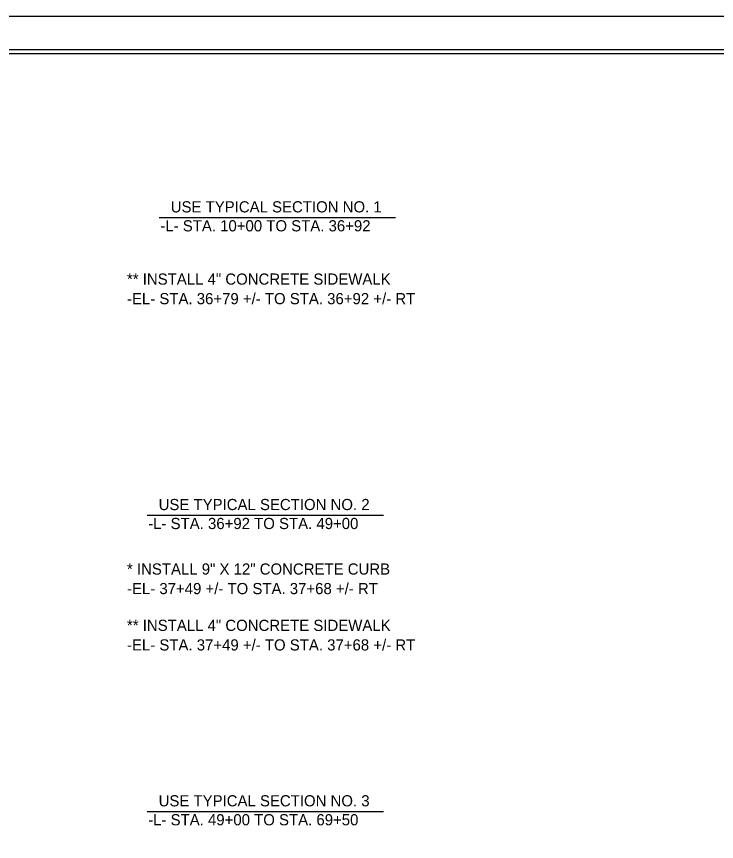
# Model space of a CAD drawing. Extents: x 1022283 to 1026986, y 174822 to 180471.
# Drawn here: x 1024632 to 1025806, y 179087 to 180471 of the extents above; entities that cross this region are included whole.
import ezdxf

# ---------------------------------------------------------------- set-up
doc = ezdxf.new("R2010")
doc.units = 0
for name, color, linetype in [('Prop Dimension', 7, 'Continuous'), ('Sheet Cutting Line CELL', 7, 'Continuous'), ('Sheet Plot Border Inside CELL', 7, 'Continuous'), ('Sheet Plot Border Outside CELL', 7, 'Continuous'), ('Sheet Typical CELL', 7, 'Continuous'), ('Typical Text Label CELL', 7, 'Continuous')]:
    doc.layers.add(name, color=color, linetype=linetype)

msp = doc.modelspace()

# ---------------------------------------------------------------- linework, layer by layer
at = {"layer": 'Sheet Cutting Line CELL'}
msp.add_line((1026493.2, 180471.5), (1022283.2, 180471.5), dxfattribs=at)
at = {"layer": 'Sheet Plot Border Inside CELL'}
msp.add_lwpolyline([(1026482, 180415.4), (1022315.7, 180415.4), (1022315.7, 177777.6), (1026482, 177777.6)], close=True, dxfattribs=at)
at = {"layer": 'Sheet Plot Border Outside CELL'}
msp.add_lwpolyline([(1026493.2, 180471.5), (1022283.2, 180471.5), (1022283.2, 177721.5), (1026493.2, 177721.5)], close=True, dxfattribs=at)
at = {"layer": 'Sheet Typical CELL'}
msp.add_lwpolyline([(1026450.7, 180409), (1022700.7, 180409), (1022700.7, 177784), (1026450.7, 177784)], close=True, dxfattribs=at)
at = {"layer": 'Typical Text Label CELL'}
for p, q in [((1024870.8, 180134.3), (1025267.4, 180134.3)), ((1024850.5, 179635), (1025247, 179635)), ((1024850.5, 179138), (1025247, 179138))]:
    msp.add_line(p, q, dxfattribs=at)

# ---------------------------------------------------------------- texts
at = {"layer": 'Prop Dimension'}
for s, p in [('-L- STA. 10+00 TO STA. 36+92', (1024872.9, 180111)), ('** INSTALL 4" CONCRETE SIDEWALK ', (1024816.9, 180021.6)), ('-EL- STA. 36+79 +/- TO STA. 36+92 +/- RT', (1024816.9, 179988.8)), ('-L- STA. 36+92 TO STA. 49+00', (1024852.5, 179611.6)), ('* INSTALL 9" X 12" CONCRETE CURB', (1024816.9, 179535.2)), ('-EL- 37+49 +/- TO STA. 37+68 +/- RT', (1024816.9, 179502.4)), ('** INSTALL 4" CONCRETE SIDEWALK ', (1024816.9, 179440.7)), ('-EL- STA. 37+49 +/- TO STA. 37+68 +/- RT', (1024816.9, 179407.9)), ('-L- STA. 49+00 TO STA. 69+50', (1024852.5, 179114.6))]:
    msp.add_text(s, height=18.75, dxfattribs=at).set_placement(p)
at = {"layer": 'Typical Text Label CELL'}
for s, p in [('USE TYPICAL SECTION NO. 1', (1024890.3, 180142.8)), ('USE TYPICAL SECTION NO. 2', (1024870, 179643.4)), ('USE TYPICAL SECTION NO. 3', (1024870, 179146.4))]:
    msp.add_text(s, height=18.75, dxfattribs=at).set_placement(p)

doc.saveas('drawing.dxf')
